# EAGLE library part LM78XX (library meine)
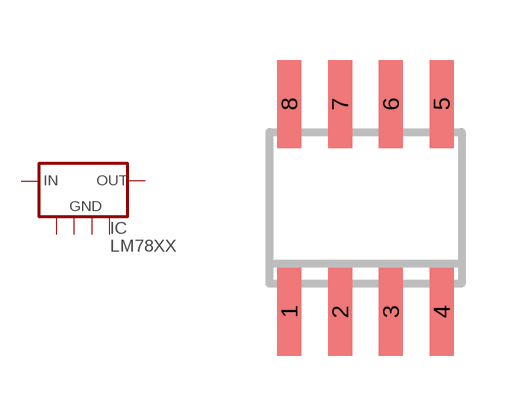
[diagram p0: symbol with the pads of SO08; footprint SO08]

Designator prefix IC

## LM78XX  [SO08]
1  OUT  pas
2  GND  in
3  GND1  in
6  GND2  in
7  GND3  in
8  IN  in

## Footprint SO08 (pad centres in mm)
smd 0.6 x 2.2: 1 -1.879,-2.64; 2 -0.609,-2.64; 3 0.661,-2.64; 4 1.931,-2.64; 5 1.931,2.56; 6 0.661,2.56; 7 -0.609,2.56; 8 -1.879,2.56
